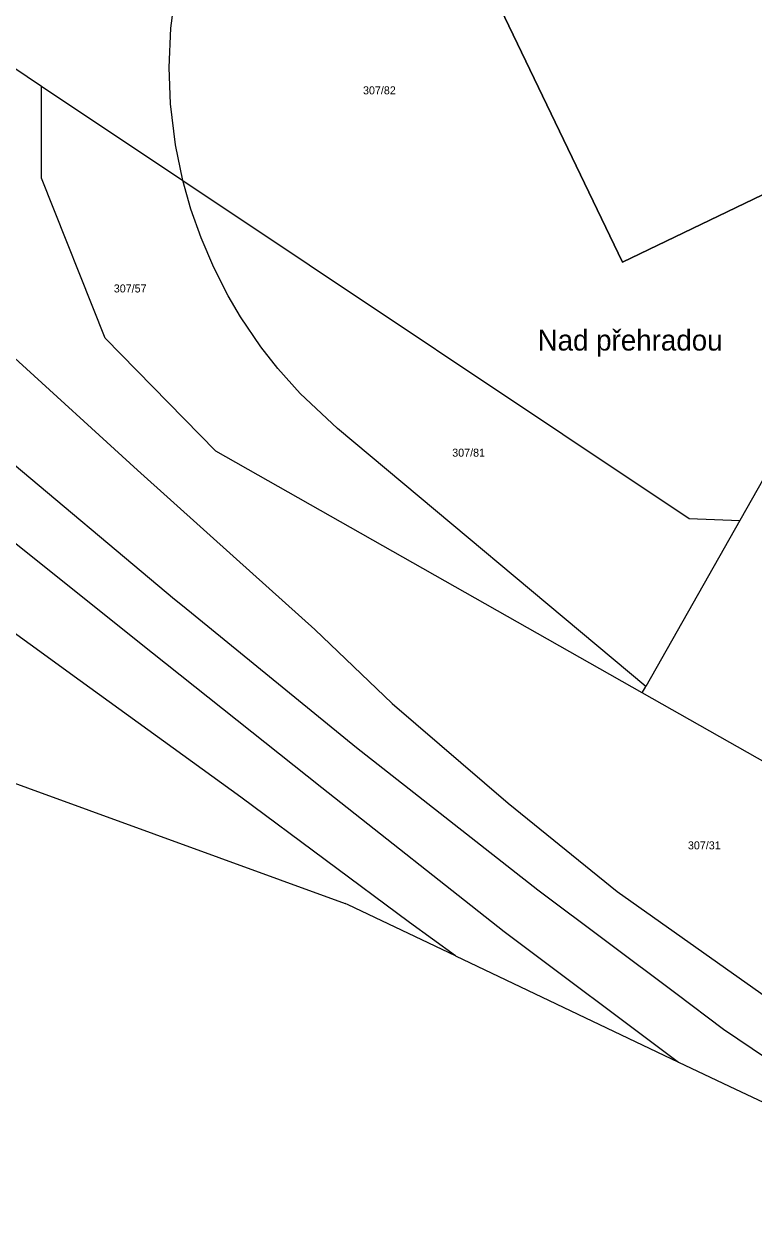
# Model space of a CAD drawing. Extents: x -882150 to -879379, y -1022570 to -1019819.
# Drawn here: x -881928.7 to -881773.8, y -1022258.6 to -1022001.3 of the extents above; entities that cross this region are included whole.
import ezdxf

# ---------------------------------------------------------------- set-up
doc = ezdxf.new("R2010")
doc.units = 0
for name, color, linetype in [('Hranice parcel', 7, 'Continuous'), ('Parcelní čísla', 7, 'Continuous'), ('Polygon budovy', 7, 'Continuous'), ('Pop  PČ popisy', 7, 'Continuous'), ('Vnitřní kresba', 7, 'Continuous')]:
    doc.layers.add(name, color=color, linetype=linetype)

msp = doc.modelspace()

# ---------------------------------------------------------------- linework, layer by layer
at = {"layer": 'Hranice parcel'}
for p, q in [((-881958.09, -1021992.35), (-881925, -1022014.45)), ((-881925, -1022014.45), (-881894.99, -1022034.5)), ((-881756.89, -1022071.5), (-881776.79, -1022106.66)), ((-881776.79, -1022106.66), (-881796.76, -1022141.96)), ((-881797.52, -1022143.3), (-881796.76, -1022141.96)), ((-881859.89, -1022188.29), (-881860.56, -1022188.05)), ((-881837.14, -1022199.13), (-881859.89, -1022188.29)), ((-881837.14, -1022199.13), (-881789.77, -1022221.69)), ((-881789.77, -1022221.69), (-881779.05, -1022226.8)), ((-881779.05, -1022226.8), (-881712.33, -1022258.57))]:
    msp.add_line(p, q, dxfattribs=at)
for points in [[(-881894.99, -1022034.5), (-881896.55, -1022026.93), (-881897.61, -1022018.24), (-881897.91, -1022010.5), (-881897.56, -1022002.19), (-881896.36, -1021992.98), (-881894.54, -1021984.78), (-881892.31, -1021977.5), (-881889.19, -1021969.65), (-881884.58, -1021960.6), (-881879.59, -1021952.79), (-881875.6, -1021947.52), (-881870.99, -1021942.21), (-881863.02, -1021934.56), (-881853.98, -1021927.65), (-881845.46, -1021922.48), (-881839.14, -1021919.34), (-881791.16, -1021900.97), (-881748.34, -1021883.67), (-881713.03, -1021868.51), (-881683.2, -1021855.06), (-881666.02, -1021847.04), (-881635.9, -1021831.46), (-881620.25, -1021823.1)], [(-881567.9, -1021992.66), (-881715.98, -1022063.86), (-881736.79, -1022020.61), (-881801.66, -1022051.83), (-881843.65, -1021964.47), (-881753.54, -1021921.14), (-881615.78, -1021854.9), (-881579.78, -1021929.76)], [(-881982.3, -1022007.45), (-881977.44, -1022017.7), (-881964.57, -1022038.79), (-881958.6, -1022045.96), (-881931.45, -1022071.52), (-881904.65, -1022096), (-881883.63, -1022114.91), (-881867, -1022129.86), (-881850.56, -1022145.58), (-881825.95, -1022166.69), (-881802.82, -1022185.46), (-881751.05, -1022222.15), (-881716.76, -1022245.07), (-881700.7, -1022254.05), (-881696.42, -1022252.15), (-881693.58, -1022248.92), (-881687.79, -1022251.45), (-881687.36, -1022251.71), (-881686.91, -1022251.9), (-881686.51, -1022252.07)], [(-881797.52, -1022143.3), (-881888, -1022092), (-881911.5, -1022068), (-881925, -1022034), (-881925, -1022014.45)], [(-881796.76, -1022141.96), (-881862.19, -1022087.15), (-881870.1, -1022079.73), (-881874.83, -1022074.43), (-881878.45, -1022069.8), (-881882.77, -1022063.43), (-881885.4, -1022058.96), (-881888.45, -1022052.96), (-881891.13, -1022046.69), (-881893.27, -1022040.6), (-881894.99, -1022034.5)], [(-881894.99, -1022034.5), (-881787.55, -1022106.27), (-881776.79, -1022106.66)], [(-881837.14, -1022199.13), (-881846.88, -1022192.05), (-881882.7, -1022165.42), (-881916.82, -1022140.71), (-881992.73, -1022085.61), (-881996.98, -1022082.52), (-882046.96, -1022047.79)], [(-882143.57, -1022124.14), (-882084.06, -1022129.12), (-881996.26, -1022145), (-881941.85, -1022158.45), (-881860.56, -1022188.05)], [(-881679.2, -1022224.6), (-881681.33, -1022220.34), (-881686, -1022211), (-881697.5, -1022200), (-881797.52, -1022143.3)]]:
    msp.add_lwpolyline(points, dxfattribs=at)
at = {"layer": 'Polygon budovy'}
msp.add_lwpolyline([(-881753.54, -1021921.14), (-881843.65, -1021964.47), (-881801.66, -1022051.83), (-881736.79, -1022020.61), (-881715.98, -1022063.86), (-881567.9, -1021992.66), (-881552.98, -1021985.49), (-881579.78, -1021929.76), (-881615.78, -1021854.9)], close=True, dxfattribs=at)
at = {"layer": 'Vnitřní kresba'}
for p, q in [((-881934.49, -1022091.75), (-881896.75, -1022123.42)), ((-881942.9, -1022101.6), (-881904.55, -1022132.34)), ((-881896.75, -1022123.42), (-881895.1, -1022124.77)), ((-881895.1, -1022124.77), (-881858.17, -1022154.92)), ((-881904.55, -1022132.34), (-881865.51, -1022163.4)), ((-881858.17, -1022154.92), (-881819.63, -1022185.12)), ((-881865.51, -1022163.4), (-881826.79, -1022193.98)), ((-881819.63, -1022185.12), (-881790.4, -1022207.06)), ((-881826.79, -1022193.98), (-881789.77, -1022221.69)), ((-881790.4, -1022207.06), (-881780.22, -1022214.7)), ((-881780.22, -1022214.7), (-881739.24, -1022242.53))]:
    msp.add_line(p, q, dxfattribs=at)

# ---------------------------------------------------------------- texts
at = {"layer": 'Parcelní čísla'}
for s, p in [('307/82', (-881856.758, -1022016.21)), ('307/57', (-881909.65, -1022058.27)), ('307/81', (-881837.825, -1022093.14)), ('307/31', (-881787.8, -1022176.52))]:
    msp.add_text(s, height=1.7, dxfattribs=at).set_placement(p)
at = {"layer": 'Pop  PČ popisy'}
msp.add_text('Nad přehradou', height=4.4, dxfattribs=at).set_placement((-881819.707, -1022070.61))

doc.saveas('drawing.dxf')
